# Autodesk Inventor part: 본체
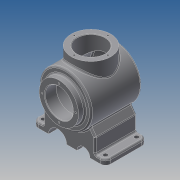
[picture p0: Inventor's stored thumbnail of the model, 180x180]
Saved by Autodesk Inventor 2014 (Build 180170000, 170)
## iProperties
Created: 2018-08
Part Number: 본체
Material: Generic
Document SubType Name: Modeling
Designer: kb542
Density: 1 g/cm^3
Appearance: Default
Author: kb542
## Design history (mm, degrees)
sketch "스케치1"
  geometry: L1 (-60, 0)-(60, 0); L2 (-60, 27)-(-60, 38); L3 (-60, 38)-(-48, 38); L4 (-48, 38)-(-48, 50); L5 (-48, 50)-(48.671, 50); L6 (-60, 27)-(-38, 27); L7 (-38, 27)-(-38, 40); L8 (-38, 40)-(42.163, 40); A1 r 116 centre (-56, 0) between (60, 0) and (48.671, 50); A2 r 106 centre (-56, 0) between (50, 0) and (42.163, 40); 3 further points
  constraints: 16 end point, 4 perpendicular, 4 point on circle, 3 parallel, 2 centre point, 2 midpoint, 2 point on line, 1 coincident, 1 horizontal, 1 vertical alignment
  dimensions: "d2" = 120 distance of L1.start L1.end; "d3" = 12 distance between parallel lines of L4 L2; "d5" = 76 diameter of L3 L1; "d6" = 100 diameter of L5 L1; "d7" = 54 diameter of L6 L1; "d8" = 80 diameter of L8 L1; "d9" = 22 distance between parallel lines of L7 L2; "d13" = 232 diameter of A1; "d14" = 10 radial gap between concentric circles of A1 A2; "d87" = 108 horizontal distance of L1.end L4.end (derived)
revolve "회전1" sketch "스케치1" stored, may be unused: angle "d15" = 90 deg
node "작업 평면1"
sketch "스케치2"
  geometry: L1 (50, -48)-(-50, -48) reference; C1 r 38 at (0, 2); 1 further point
  constraints: 1 centre point, 1 vertical alignment
  dimensions: "d17" = 50 distance from line of L1 C1.centre; "d18" = 76 diameter of C1
extrude "돌출1" join sketch "스케치2" stored distance "d19" = 10; taper "d20" = 0 deg
sketch "스케치3"
  geometry: C1 r 38 at (0, 0) reference; C2 r 27 at (0, 0); 1 further point
  constraints: 1 centre point, 1 coincident
  dimensions: "d21" = 54 diameter of C2
extrude "돌출2" cut sketch "스케치3" stored distance "d22" = 10; taper "d23" = 0 deg
node "작업 평면3"
  node "작업 평면2"
sketch "스케치4"
  geometry: L1 (-50, -43.437)-(-50, -72); L2 (-50, -72)-(-70, -72); L3 (-70, -72)-(-70, -82); L4 (-70, -82)-(70, -82); L5 (70, -82)-(70, -72); L6 (70, -72)-(50, -72); L7 (50, -72)-(50, -43.437); L8 (-70, -72)-(-40.304, -29.59); L9 (70, -72)-(40.304, -29.59); L10 (-50, -43.437)-(-40.304, -29.59); L11 (50, -43.437)-(40.304, -29.59); A1 r 50 centre (0, 0) between (-40.304, -29.59) and (40.304, -29.59) reference; A2 r 50 centre (0, 0) between (-40.304, -29.59) and (40.304, -29.59) reference; 2 further points
  constraints: 22 end point, 6 perpendicular, 4 point on circle, 2 collinear, 2 point on line, 1 midpoint, 1 vertical, 1 vertical alignment
  dimensions: "d27" = 20 distance of L1.end L2.end; "d29" = 20 distance of L5.end L6.end; "d30" = 82 distance from line of L4 point (0, 0); "d31" = 10 distance of L2.end L3.end; "d32" = 10 distance between parallel lines of L4 L6; "d33" = 140 distance of L3.end L4.end; "d39" = 35 deg angle of L9 L5; "d40" = 35 deg angle of L8 L3
extrude "돌출3" join sketch "스케치4" stored distance "d41" = 80; taper "d42" = 0 deg
node "작업 평면4"
sketch "스케치6"
  geometry: C1 r 50 at (0, 0) reference; C2 r 50 at (0, 0) reference; C3 r 32.5 at (0, 0); 1 further point
  constraints: 1 centre point, 1 coincident, 1 other
  dimensions: "d46" = 65 diameter of C3
feature "엠보싱2" sketch "스케치6" dims "d2" = 120, "d3" = 12, "d5" = 76, "d6" = 100, "d7" = 54, "d8" = 80, "d9" = 22, "d13" = 232, "d14" = 10, "d47" = 0.5, "d48" = 0, "d87" = 108 (derived)
sketch "스케치7"
  geometry: L1 (70, 82)-(-70, 82) reference; L2 (-70, 72)-(-50, 72) reference; L3 (0, 0)-(0, 94.175); C1 r 12.5 at (27.5, 82); C2 r 17.5 at (-22.5, 82); A1 r 50 centre (0, 0) between (40.304, 29.59) and (-40.304, 29.59) reference
  constraints: 2 centre point, 2 end point, 2 point on line, 1 perpendicular
  dimensions: "d49" = 25 diameter of C1; "d50" = 35 diameter of C2; "d51" = 27.5 distance from line of L3 C1.centre; "d52" = 94.17488 distance of L3.start L3.end; "d53" = 22.5 distance from line of C2.centre L3
extrude "돌출4" cut sketch "스케치7" stored distance "d54" = 80; taper "d55" = 0 deg
fillet "모깎기1" dims "d56" = 10
sketch "스케치8"
  geometry: L1 (-120, 70)-(-120, 10) reference; L2 (-100, 0)-(-110, 0) reference; L3 (-100, 80)-(-100, 0) reference; L4 (-110, 80)-(-100, 80) reference; A1 r 10 centre (10, 70) between (20, 70) and (10, 80) reference; A2 r 10 centre (10, 10) between (10, 0) and (20, 10) reference; A3 r 10 centre (-110, 70) between (-110, 80) and (-120, 70) reference; A4 r 10 centre (-110, 10) between (-120, 10) and (-110, 0) reference; 5 further points
  constraints: 4 coincident
hole "구멍1" sketch "스케치8" at (10, 70), (10, 10), (-110, 10), (-110, 70) diameter "d57" = 8; stored, may be unused: countersink angle "d61" = 90 deg, drill point angle "d63" = 118 deg; dims "d58" = 6, "d59" = 4, "d60" = 2, "d62" = 8
sketch "스케치9"
  geometry: C1 r 38 at (0, 0) reference; A1 r 32.5 centre (0, 0) between (0, 32.5) and (32.5, 0); 2 further points
  constraints: 4 point on circle, 2 horizontal alignment, 2 vertical alignment, 1 centre point, 1 coincident
  dimensions: "d64" = 65 diameter of A1
hole "구멍2" sketch "스케치9" at (0, 32.5), (32.5, 0), (0, -32.5), (-32.5, 0) diameter "d65" = 3.242; stored, may be unused: countersink angle "d69" = 90 deg, drill point angle "d71" = 118 deg; dims "d66" = 8, "d67" = 4, "d68" = 2, "d70" = 10
sketch "스케치10"
  geometry: C1 r 27 at (0, 0) reference; C2 r 38 at (0, 0) reference; A1 r 32.5 centre (0, 0) between (0, 32.5) and (32.5, 0); 3 further points
  constraints: 4 point on circle, 2 horizontal alignment, 2 vertical alignment, 1 centre point, 1 coincident
  dimensions: "d72" = 65 diameter of A1
hole "구멍3" sketch "스케치10" at (0, 32.5), (32.5, 0), (0, -32.5), (-32.5, 0) diameter "d73" = 3.242; stored, may be unused: countersink angle "d77" = 90 deg, drill point angle "d79" = 118 deg; dims "d74" = 8, "d75" = 4, "d76" = 2, "d78" = 10
fillet "모깎기2" dims "d80" = 3
fillet "모깎기3" dims "d81" = 3
fillet "모깎기4" dims "d82" = 3
chamfer "모따기1" distance "d83" = 1; stored, may be unused: second distance "d84" = 2, angle "d85" = 45 deg
fillet "모깎기5" dims "d86" = 3
node "솔리드1"
node "투영된 루프1"
node "투영된 루프2"
node "투영된 루프3"
other parameters: "d16" = 65, "d24" = -54
